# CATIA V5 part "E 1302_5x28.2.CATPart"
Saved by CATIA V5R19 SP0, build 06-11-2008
Part number: E 1302_5x28.2
Nomenclature: E 1302_5x28
Source: Unknown
Description: PART-E 1302_5x28-DESC
Bounding box of the stored display mesh (mm): x -2.5 to 2.5, y -2.5 to 2.5, z 0 to 28
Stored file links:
  C:\Users\jsmid\Desktop\DP_Smidak_Forma LEGO\E 1302_5x28.2.CATPart
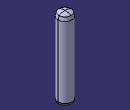
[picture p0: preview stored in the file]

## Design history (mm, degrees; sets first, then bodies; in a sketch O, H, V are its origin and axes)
Body1 "E 1302_5x28" (main body)
  Solid1: solid without history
